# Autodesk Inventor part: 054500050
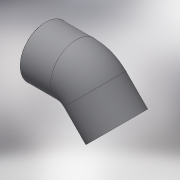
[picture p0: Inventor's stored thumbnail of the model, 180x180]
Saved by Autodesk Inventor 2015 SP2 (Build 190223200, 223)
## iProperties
Created: 2017-10
Part Number: 054500050
Material: Generic
Description: PLASSON 45° ELBOW CEMENT PVC 50
Document SubType Name: Modeling
Designer: KIM
Density: 1 g/cm^3
Appearance: Default
Author: KIM
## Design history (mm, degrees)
derived "054500.ipt"
feature "Solid1::054500.ipt"
tag "TaggingFeature1"
body "Solid1"
other parameters: "d1" = 59, "d5" = 45, "d7" = 0.5, "d9" = 59, "d13" = 135 deg, "d18" = 12, "d19" = 45 deg, "d21" = 31, "d22" = 0, "d24" = 135 deg, "d26" = 45, "d27" = 45 deg, "d28" = 43, "E_" = 59, "H_" = 35, "l_" = 31, "Z_" = 12
